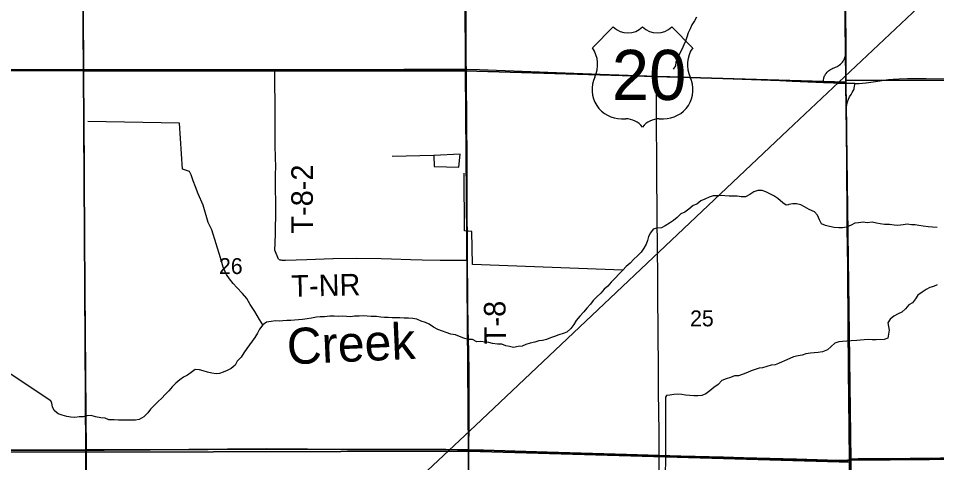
# Model space of a CAD drawing. Extents: x 0 to 34, y 0 to 22.
# Drawn here: x 5.327 to 7.743, y 16.618 to 17.786 of the extents above; entities that cross this region are included whole.
import ezdxf

# ---------------------------------------------------------------- set-up
doc = ezdxf.new("R2010")
doc.units = 0
for name, color, linetype in [('Default', 7, 'Continuous'), ('GM_X_County_Road', 7, 'Continuous'), ('GM_X_Minor_Lake', 7, 'Continuous'), ('GM_X_Minor_River', 7, 'Continuous'), ('GM_X_Minor_River_Text', 7, 'Continuous'), ('GM_X_Rail_Line', 7, 'Continuous'), ('GM_X_Section', 7, 'Continuous'), ('GM_X_Section_Text', 7, 'Continuous'), ('GM_X_State_Route', 7, 'Continuous'), ('GM_X_Township_Road', 7, 'Continuous'), ('GM_X_Township_Road_Text', 7, 'Continuous'), ('GM_X_US_Location', 7, 'Continuous'), ('GM_X_US_Route', 7, 'Continuous'), ('GM_X_US_Shield', 7, 'Continuous')]:
    doc.layers.add(name, color=color, linetype=linetype)

msp = doc.modelspace()

# ---------------------------------------------------------------- linework, layer by layer
at = {"layer": 'Default'}
for points in [[(5.2793, 16.6503), (5.5058, 16.651), (5.5529, 16.6511), (5.6741, 16.6516), (5.9788, 16.6539), (6.0877, 16.6534), (6.1934, 16.6525), (6.3644, 16.6524), (6.4514, 16.6525), (6.5115, 16.6515), (6.5509, 16.6508), (6.7187, 16.6456), (6.9269, 16.6394), (7.0127, 16.6367), (7.0699, 16.6349), (7.1818, 16.6319), (7.2346, 16.6304), (7.3745, 16.6268), (7.4553, 16.6243), (7.4925, 16.623), (7.5049, 16.6234), (7.5087, 16.6241), (7.5134, 16.6254), (7.5132, 16.6298), (7.5127, 16.7012), (7.5126, 16.7199), (7.512, 16.7728), (7.5112, 16.8754), (7.5101, 16.9656), (7.5098, 17.006), (7.5099, 17.0121), (7.5099, 17.0339), (7.5094, 17.0649), (7.5089, 17.1334), (7.5078, 17.236), (7.5076, 17.2888), (7.5069, 17.3759), (7.5061, 17.4412), (7.506, 17.4536), (7.5054, 17.5157), (7.5051, 17.5394), (7.505, 17.5475), (7.5036, 17.6162), (7.504, 17.6965), (7.5041, 17.701), (7.5038, 17.739), (7.5032, 17.7822), (7.5006, 17.9615)], [(7.5006, 17.9615), (7.5032, 17.7822), (7.5038, 17.739), (7.5041, 17.701), (7.504, 17.6965), (7.5036, 17.6162), (7.505, 17.5475), (7.5051, 17.5394), (7.5054, 17.5157), (7.506, 17.4536), (7.5061, 17.4412), (7.5069, 17.3759), (7.5076, 17.2888), (7.5078, 17.236), (7.5089, 17.1334), (7.5094, 17.0649), (7.5099, 17.0339), (7.5099, 17.0121), (7.5098, 17.006), (7.5101, 16.9656), (7.5112, 16.8754), (7.512, 16.7728), (7.5126, 16.7199), (7.5127, 16.7012), (7.5132, 16.6298), (7.5134, 16.6254), (7.5154, 16.6261), (7.5175, 16.6266), (7.5197, 16.6269), (7.5217, 16.6271), (7.5232, 16.6271), (7.5362, 16.6274), (7.5767, 16.6277), (7.6731, 16.6285), (7.8317, 16.6301)], [(7.5138, 16.5271), (7.5134, 16.6254), (7.5087, 16.6241), (7.5049, 16.6234), (7.4925, 16.623), (7.4553, 16.6243), (7.3745, 16.6268), (7.2346, 16.6304), (7.1818, 16.6319), (7.0699, 16.6349), (7.0127, 16.6367), (6.9269, 16.6394), (6.7187, 16.6456), (6.5509, 16.6508), (6.5115, 16.6515), (6.4514, 16.6525), (6.3644, 16.6524), (6.1934, 16.6525), (6.0877, 16.6534), (5.9788, 16.6539), (5.6741, 16.6516), (5.5529, 16.6511), (5.5058, 16.651), (5.2793, 16.6503)], [(7.8317, 16.6301), (7.6731, 16.6285), (7.5767, 16.6277), (7.5362, 16.6274), (7.5232, 16.6271), (7.5217, 16.6271), (7.5197, 16.6269), (7.5175, 16.6266), (7.5154, 16.6261), (7.5134, 16.6254), (7.5138, 16.5271), (7.5145, 16.4463), (7.5165, 16.1851), (7.5171, 16.0545), (7.5184, 15.927), (7.5192, 15.8554), (7.5206, 15.6813), (7.5216, 15.6399), (7.5244, 14.8701), (7.5225, 14.1), (8.9, 14.1)]]:
    msp.add_lwpolyline(points, dxfattribs=at)
at = {"layer": 'GM_X_County_Road'}
for points in [[(7.4449, 17.618), (7.4449, 17.6219), (7.4452, 17.6249), (7.4456, 17.628), (7.4459, 17.6297), (7.447, 17.6328), (7.448, 17.6354), (7.4491, 17.6372), (7.4506, 17.6395), (7.4524, 17.6418), (7.4546, 17.6445), (7.4569, 17.6466), (7.4586, 17.6483), (7.4611, 17.65), (7.4638, 17.6517), (7.4668, 17.6536), (7.4699, 17.6552), (7.4734, 17.6567), (7.4765, 17.6578), (7.4794, 17.659), (7.4816, 17.6602), (7.4841, 17.6616), (7.4866, 17.6634), (7.49, 17.6659), (7.4949, 17.6711), (7.4969, 17.6738), (7.4987, 17.677), (7.4994, 17.6782), (7.5006, 17.6808), (7.5016, 17.6838), (7.5029, 17.688), (7.5036, 17.6916), (7.5042, 17.6959), (7.5043, 17.7004), (7.5041, 17.7384), (7.5035, 17.7817), (7.5008, 17.961)], [(7.5039, 17.6156), (7.4834, 17.616), (7.4582, 17.6174), (7.4449, 17.618)], [(7.5277, 17.6151), (7.5268, 17.6151), (7.5039, 17.6156)], [(7.5136, 16.6249), (7.5134, 16.6292), (7.513, 16.7007), (7.5129, 16.7193), (7.5123, 16.7722), (7.5114, 16.8748), (7.5103, 16.965), (7.51, 17.0054), (7.5101, 17.0115), (7.5101, 17.0333), (7.5096, 17.0644), (7.5092, 17.1328), (7.5081, 17.2354), (7.5079, 17.2883), (7.5071, 17.3753), (7.5063, 17.4406), (7.5063, 17.4531), (7.5056, 17.5151), (7.5053, 17.5388), (7.5052, 17.5469), (7.5054, 17.5527), (7.5063, 17.5594), (7.5081, 17.567), (7.5109, 17.5743), (7.5138, 17.5799), (7.5175, 17.5864), (7.5208, 17.5918), (7.523, 17.5954), (7.5248, 17.5987), (7.5256, 17.6009), (7.5261, 17.6029), (7.5268, 17.6073), (7.5273, 17.6123), (7.5277, 17.6151)], [(5.0035, 16.6486), (5.065, 16.6487), (5.2795, 16.6497), (5.5061, 16.6504)], [(5.5061, 16.6504), (5.5531, 16.6506), (5.6744, 16.651), (5.9791, 16.6533), (6.0879, 16.6528), (6.1936, 16.6519), (6.3646, 16.6519), (6.4517, 16.652), (6.5118, 16.6509)], [(6.5118, 16.6509), (6.5511, 16.6502), (6.7189, 16.6451), (6.9272, 16.6389), (7.0129, 16.6361)], [(7.0129, 16.6361), (7.0701, 16.6343), (7.182, 16.6313), (7.2348, 16.6298), (7.3747, 16.6263), (7.4555, 16.6237), (7.4927, 16.6225), (7.5051, 16.6228), (7.5089, 16.6235), (7.5136, 16.6249)], [(7.5136, 16.6249), (7.5156, 16.6255), (7.5177, 16.626), (7.5199, 16.6263), (7.5219, 16.6265), (7.5235, 16.6265), (7.5365, 16.6268), (7.5769, 16.6271), (7.6733, 16.628), (7.8319, 16.6295), (7.9034, 16.63), (7.9967, 16.6306), (8.0838, 16.6311), (8.1584, 16.6316), (8.2952, 16.6318), (8.3854, 16.6323), (8.4383, 16.6327), (8.4973, 16.6329), (8.6217, 16.6331), (8.6592, 16.6332)], [(7.5219, 15.6393), (7.5208, 15.6808), (7.5195, 15.8549), (7.5186, 15.9264), (7.5174, 16.0539), (7.5167, 16.1845), (7.5147, 16.4457), (7.5141, 16.5265), (7.5136, 16.6249)]]:
    msp.add_lwpolyline(points, dxfattribs=at)
at = {"layer": 'GM_X_Minor_Lake'}
msp.add_line((6.4205, 17.4253), (6.4213, 17.3969), dxfattribs=at)
msp.add_lwpolyline([(6.4213, 17.3969), (6.4861, 17.3947), (6.4891, 17.4292), (6.4205, 17.4253)], dxfattribs=at)
at = {"layer": 'GM_X_Minor_River'}
for points in [[(7.1107, 17.79), (7.1056, 17.7798), (7.0987, 17.7692), (7.0944, 17.759), (7.089, 17.7484), (7.0855, 17.7371), (7.0823, 17.7265), (7.0777, 17.7167), (7.0726, 17.7042), (7.066, 17.6929), (7.0621, 17.6823), (7.0571, 17.6725), (7.0558, 17.6619), (7.0493, 17.6532)], [(5.97, 16.9801), (5.9618, 16.9943), (5.9492, 17.0153), (5.9369, 17.034), (5.9283, 17.0492), (5.9167, 17.063), (5.9017, 17.0783), (5.8924, 17.0887), (5.8823, 17.1013), (5.8748, 17.1128), (5.8659, 17.1322), (5.8586, 17.1566), (5.836, 17.23), (5.8267, 17.2498), (5.8136, 17.2951), (5.8002, 17.3249), (5.7932, 17.3435), (5.7874, 17.3591), (5.7818, 17.3751), (5.7774, 17.3839), (5.7589, 17.3894), (5.7511, 17.5109), (5.5104, 17.5148)], [(6.4205, 17.4253), (6.3105, 17.423)], [(6.9171, 17.124), (6.5215, 17.1386), (6.5202, 17.2259), (6.5005, 17.2276), (6.5003, 17.379)], [(7.3534, 17.2956), (7.3471, 17.2954), (7.338, 17.3008), (7.3253, 17.3127), (7.3143, 17.3197), (7.3042, 17.3251), (7.2936, 17.3305), (7.2834, 17.334), (7.2724, 17.3334), (7.2618, 17.3297), (7.2511, 17.3229), (7.2404, 17.317), (7.229, 17.3171), (7.218, 17.3187), (7.2082, 17.3188), (7.1968, 17.3189), (7.1858, 17.3198), (7.176, 17.3207), (7.1654, 17.3196), (7.1551, 17.3197), (7.1441, 17.316), (7.1334, 17.3112), (7.1227, 17.306), (7.112, 17.2974), (7.1025, 17.2945), (7.091, 17.2843), (7.08, 17.2768), (7.0697, 17.272), (7.0601, 17.263), (7.0505, 17.2551), (7.0402, 17.2473), (7.0291, 17.2405), (7.0188, 17.2353), (7.0071, 17.2347), (6.9968, 17.2321), (6.9899, 17.2223), (6.9845, 17.2125), (6.9825, 17.2023), (6.9785, 17.1921), (6.9724, 17.1823), (6.9658, 17.1713), (6.9562, 17.1616), (6.9459, 17.153), (6.9363, 17.1424), (6.9263, 17.1338), (6.9171, 17.124), (6.9079, 17.1142), (6.8968, 17.103), (6.8864, 17.0925), (6.878, 17.0819), (6.868, 17.0737), (6.8592, 17.0631), (6.8489, 17.0541), (6.8389, 17.0444), (6.832, 17.0346), (6.8227, 17.0244), (6.8151, 17.0146), (6.8039, 17.003), (6.7947, 16.9917), (6.7881, 16.9815), (6.7808, 16.9709), (6.7701, 16.9612), (6.7606, 16.9575), (6.7492, 16.9538), (6.7377, 16.9494), (6.7271, 16.946), (6.7168, 16.942), (6.7062, 16.9387), (6.6963, 16.938), (6.6856, 16.9343), (6.6735, 16.9322), (6.6624, 16.9285), (6.6525, 16.924), (6.6419, 16.923), (6.6301, 16.9208), (6.6192, 16.9236), (6.6093, 16.9252), (6.5988, 16.9295), (6.5874, 16.9292), (6.5749, 16.9312), (6.5651, 16.9336), (6.5548, 16.9349), (6.5435, 16.9365), (6.5336, 16.9358), (6.5216, 16.9416), (6.5102, 16.9418), (6.4992, 16.9453), (6.4879, 16.9496), (6.4773, 16.9535), (6.4645, 16.9559), (6.4524, 16.9602), (6.4426, 16.9633), (6.4309, 16.968), (6.4196, 16.9745), (6.4079, 16.9819), (6.3981, 16.9865), (6.3871, 16.9897), (6.3758, 16.9951), (6.3645, 16.9971), (6.3531, 16.9976), (6.3417, 16.9977)], [(7.7445, 17.2361), (7.7316, 17.237), (7.7206, 17.2383), (7.7074, 17.2399), (7.6961, 17.2419), (7.6862, 17.2432), (7.6764, 17.2433), (7.665, 17.2449), (7.6544, 17.2431), (7.6407, 17.2418), (7.6309, 17.2423), (7.6188, 17.2439), (7.6059, 17.2444), (7.5946, 17.246), (7.5843, 17.2477), (7.5734, 17.2501), (7.5597, 17.2483), (7.5491, 17.2503), (7.5374, 17.2485), (7.5279, 17.2475), (7.518, 17.2427), (7.5058, 17.2371), (7.4951, 17.2357), (7.4857, 17.235), (7.4736, 17.2367), (7.4611, 17.2387), (7.4501, 17.2415), (7.4396, 17.2461), (7.4348, 17.2564), (7.4296, 17.2683), (7.4214, 17.2778), (7.4075, 17.284), (7.3954, 17.2906), (7.3853, 17.296), (7.3743, 17.2984), (7.3641, 17.2989), (7.3542, 17.2964), (7.3534, 17.2956)], [(7.7441, 17.0852), (7.7342, 17.0811), (7.7247, 17.0782), (7.7148, 17.0733), (7.7048, 17.0658), (7.6933, 17.058), (7.6872, 17.0482), (7.6791, 17.0384), (7.6695, 17.0328), (7.6611, 17.0219), (7.6515, 17.0133), (7.6412, 17.0092), (7.6301, 17.0029), (7.6202, 16.9954), (7.6147, 16.9852), (7.6161, 16.9754), (7.6175, 16.9659), (7.6163, 16.9553), (7.6142, 16.9454), (7.6047, 16.9413), (7.5835, 16.9408), (7.5736, 16.9405), (7.563, 16.9414), (7.552, 16.9411), (7.5422, 16.9397), (7.5327, 16.9391), (7.5183, 16.9377), (7.5069, 16.9374), (7.4951, 16.9368), (7.4853, 16.9354), (7.4754, 16.9321), (7.4654, 16.9231), (7.4555, 16.9148), (7.4429, 16.9089), (7.4307, 16.9071), (7.4205, 16.9069), (7.4106, 16.9054), (7.3989, 16.904), (7.3893, 16.9), (7.3783, 16.8986), (7.3666, 16.8957)], [(6.3417, 16.9977), (6.3311, 16.9989), (6.3213, 16.9987), (6.3107, 16.9984), (6.3001, 16.9992), (6.2902, 16.9993), (6.2804, 17.0002), (6.2694, 17.0018), (6.2554, 17.0023), (6.2444, 17.0028), (6.2341, 17.0037), (6.2235, 17.003), (6.2114, 17.0028), (6.2008, 17.0014), (6.1905, 17.0022), (6.1807, 17.0027), (6.1693, 17.0021), (6.1579, 17.0026), (6.1462, 17.0031), (6.1325, 17.0017), (6.1211, 17.001), (6.1113, 17), (6.098, 16.9978), (6.0866, 16.9957), (6.0744, 16.9939), (6.0646, 16.9932), (6.0536, 16.9926), (6.0441, 16.9912), (6.0331, 16.9913), (6.0232, 16.9906), (6.0137, 16.9903), (6.0039, 16.9908), (5.9921, 16.9894), (5.9799, 16.9869), (5.97, 16.9801), (5.9615, 16.9688), (5.9565, 16.9586), (5.9492, 16.9473), (5.9422, 16.9375), (5.9353, 16.9274), (5.9284, 16.9176), (5.9207, 16.9063), (5.9137, 16.8949), (5.9026, 16.8848), (5.8972, 16.8742), (5.8872, 16.8652), (5.8769, 16.8604), (5.8663, 16.856), (5.8567, 16.8523), (5.8473, 16.8512), (5.8359, 16.8528), (5.8249, 16.856), (5.8136, 16.8595), (5.8038, 16.8619), (5.792, 16.8628), (5.7821, 16.8545), (5.7718, 16.8482), (5.7615, 16.8422), (5.7519, 16.8351), (5.7416, 16.8265), (5.7316, 16.8171), (5.7232, 16.8065), (5.7132, 16.7968), (5.7044, 16.787), (5.6948, 16.7787), (5.6852, 16.7693), (5.6749, 16.7588), (5.6675, 16.749), (5.6572, 16.7381), (5.6453, 16.731), (5.6355, 16.7292), (5.6203, 16.7298), (5.6104, 16.7291), (5.5998, 16.7296), (5.5904, 16.7293), (5.5794, 16.7302), (5.565, 16.7307), (5.5552, 16.7346), (5.5442, 16.7358), (5.5302, 16.7386), (5.5185, 16.7414), (5.5078, 16.7407), (5.4976, 16.7382), (5.487, 16.7383), (5.4756, 16.7361), (5.465, 16.737), (5.4544, 16.739), (5.4423, 16.7422), (5.4321, 16.746), (5.4216, 16.7549), (5.4175, 16.7644), (5.415, 16.7739), (5.4128, 16.7804)], [(5.4128, 16.7804), (5.1824, 16.9329)], [(7.3406, 16.8849), (7.3367, 16.8831), (7.3272, 16.8786), (7.3177, 16.8753), (7.3078, 16.8739), (7.285, 16.8673), (7.2755, 16.8662), (7.2546, 16.8596), (7.2451, 16.8551), (7.2336, 16.8507), (7.2214, 16.8459), (7.2112, 16.846), (7.2009, 16.8419), (7.1891, 16.8382), (7.1781, 16.8334), (7.1685, 16.8236), (7.1566, 16.815), (7.1459, 16.8068), (7.1356, 16.7985), (7.1249, 16.7941), (7.1147, 16.7938), (7.1041, 16.7936), (7.0939, 16.7944), (7.0825, 16.7953), (7.0723, 16.7973), (7.0613, 16.7978), (7.0518, 16.7967), (7.0412, 16.7953), (7.0322, 16.7945), (7.0297, 16.7897)], [(7.3666, 16.8957), (7.3406, 16.8849)], [(7.0297, 16.7897), (7.029, 16.4232), (7.0051, 16.4238), (7.0024, 16.1814)]]:
    msp.add_lwpolyline(points, dxfattribs=at)
at = {"layer": 'GM_X_Rail_Line'}
msp.add_lwpolyline([(5.6036, 14.1), (5.6231, 15.2124), (5.6254, 15.4429), (5.6392, 15.5731), (5.6554, 15.6619), (5.6784, 15.7322), (5.7095, 15.8198), (5.7429, 15.8889), (5.7752, 15.9442), (5.8121, 16.0007), (5.8512, 16.0606), (5.9042, 16.1217), (5.9987, 16.2174), (6.5299, 16.7153), (7.3509, 17.4922), (8.0819, 18.1807), (8.7161, 18.7707), (8.9, 18.9438)], dxfattribs=at)
at = {"layer": 'GM_X_Section'}
for points in [[(4.4846, 18.6535), (5.4908, 18.6512), (5.4987, 17.6483), (4.4933, 17.6509)], [(5.4908, 18.6512), (6.4992, 18.6508), (6.5031, 17.6487), (5.4987, 17.6483)], [(6.4992, 18.6508), (7.4929, 18.6076), (7.5039, 17.6243), (7.5038, 17.6183), (6.5031, 17.6487)], [(7.4927, 18.6151), (8.6395, 18.6159), (8.6491, 17.6213), (7.5039, 17.6243), (7.4929, 18.6076)], [(4.4933, 17.6509), (5.4987, 17.6483), (5.5052, 16.6454), (4.5021, 16.6472)], [(5.4987, 17.6483), (6.5031, 17.6487), (6.5111, 16.648), (5.5052, 16.6454)], [(6.5031, 17.6487), (7.5038, 17.6183), (7.5172, 16.6244), (7.5171, 16.6191), (6.5111, 16.648)], [(7.5039, 17.6243), (8.6491, 17.6213), (8.6573, 16.6339), (7.5172, 16.6244), (7.5038, 17.6183)], [(4.5021, 16.6472), (5.5052, 16.6454), (5.5125, 15.6443), (4.5104, 15.6416)], [(5.5052, 16.6454), (6.5111, 16.648), (6.5138, 15.6467), (5.5125, 15.6443)], [(6.5111, 16.648), (7.5171, 16.6191), (7.5223, 15.6321), (6.5138, 15.6467)], [(7.5172, 16.6244), (8.6573, 16.6339), (8.6614, 15.6262), (7.5223, 15.6321), (7.5171, 16.6191)]]:
    msp.add_lwpolyline(points, close=True, dxfattribs=at)
at = {"layer": 'GM_X_State_Route'}
for points in [[(5.4994, 17.652), (5.4992, 17.672), (5.4983, 17.787), (5.4981, 17.8181), (5.4981, 17.828), (5.4981, 17.8523), (5.4963, 17.9797), (5.4953, 18.0979), (5.494, 18.2004), (5.4935, 18.2378), (5.4913, 18.4833), (5.4897, 18.6357), (5.4896, 18.6535), (5.4893, 18.6854), (5.4887, 18.8626), (5.4886, 18.9093), (5.4885, 18.9621), (5.4881, 19.0056), (5.4877, 19.0709), (5.4874, 19.1734), (5.4864, 19.4408)], [(5.5061, 16.6504), (5.5054, 16.7424), (5.5044, 16.8606), (5.504, 16.9569), (5.5017, 17.3207), (5.5012, 17.4046), (5.5006, 17.501), (5.4994, 17.652)], [(5.507, 16.5341), (5.5061, 16.6504)]]:
    msp.add_lwpolyline(points, dxfattribs=at)
at = {"layer": 'GM_X_Township_Road'}
for points in [[(6.5059, 17.6525), (6.5054, 17.6677), (6.5051, 17.7796), (6.5047, 17.8728), (6.5046, 17.9008), (6.5044, 17.9443), (6.5042, 18.0344), (6.5029, 18.1432), (6.502, 18.1898), (6.5016, 18.2458), (6.5011, 18.3763), (6.5004, 18.4416), (6.5, 18.5131), (6.4994, 18.6001), (6.4986, 18.6529), (6.4986, 18.6541)], [(6.0115, 17.1532), (6.0023, 17.1765), (6.003, 17.1953), (6.0036, 17.2203), (6.0042, 17.2828), (6.004, 17.3579), (6.0036, 17.3786), (6.0042, 17.394), (6.0032, 17.4502), (6.0031, 17.4689), (6.0027, 17.5407), (6.0026, 17.5688), (6.0022, 17.6094), (6.0022, 17.6343), (6.002, 17.6406), (6.0017, 17.6519)], [(6.5089, 17.1507), (6.5084, 17.1922), (6.5081, 17.2854), (6.5076, 17.4346), (6.507, 17.4967), (6.5062, 17.6428), (6.5059, 17.6525)], [(7.0129, 16.6361), (7.0128, 16.6482), (7.0125, 16.698), (7.0115, 16.8037), (7.0108, 16.8877), (7.0103, 16.9375), (7.0093, 17.0836), (7.009, 17.1178), (7.0085, 17.1707), (7.0069, 17.3759), (7.0066, 17.4195), (7.0062, 17.5035), (7.0056, 17.5532), (7.005, 17.6248), (7.005, 17.6346)], [(6.0115, 17.1532), (6.0147, 17.1516), (6.0176, 17.1508), (6.0207, 17.1503), (6.03, 17.1501), (6.0579, 17.1513), (6.0858, 17.1525), (6.1541, 17.1545), (6.1551, 17.1545)], [(6.1551, 17.1545), (6.2161, 17.1553), (6.2813, 17.1548), (6.3092, 17.1538), (6.3588, 17.1517), (6.3898, 17.1512), (6.4364, 17.1507), (6.5089, 17.1507)], [(6.5118, 16.6509), (6.5119, 16.6576), (6.513, 16.7167), (6.5131, 16.7695), (6.5127, 16.8534), (6.512, 16.9124), (6.5108, 16.9684), (6.5097, 17.043), (6.5092, 17.0709), (6.5091, 17.1362), (6.5089, 17.1507)], [(5.0035, 16.6486), (5.065, 16.6487), (5.2795, 16.6497), (5.5061, 16.6504)], [(5.5061, 16.6504), (5.5531, 16.6506), (5.6744, 16.651), (5.9791, 16.6533), (6.0879, 16.6528), (6.1936, 16.6519), (6.3646, 16.6519), (6.4517, 16.652), (6.5118, 16.6509)], [(6.5149, 16.1915), (6.5149, 16.1968), (6.5147, 16.2216), (6.5142, 16.2961), (6.5127, 16.4952), (6.5118, 16.6008), (6.5118, 16.6509)], [(6.5118, 16.6509), (6.5511, 16.6502), (6.7189, 16.6451), (6.9272, 16.6389), (7.0129, 16.6361)], [(7.0152, 16.1383), (7.0155, 16.1476), (7.0159, 16.2345), (7.0139, 16.4585), (7.0129, 16.5891), (7.0125, 16.6233), (7.0129, 16.6361)], [(7.0129, 16.6361), (7.0701, 16.6343), (7.182, 16.6313), (7.2348, 16.6298), (7.3747, 16.6263), (7.4555, 16.6237), (7.4927, 16.6225), (7.5051, 16.6228), (7.5089, 16.6235), (7.5136, 16.6249)]]:
    msp.add_lwpolyline(points, dxfattribs=at)
at = {"layer": 'GM_X_US_Route'}
msp.add_line((7.3626, 17.6215), (7.4449, 17.618), dxfattribs=at)
for points in [[(5.0334, 17.6517), (5.2384, 17.6517), (5.4056, 17.6521), (5.4994, 17.652)], [(5.4994, 17.652), (5.5479, 17.6519), (5.623, 17.6517), (5.6849, 17.6518), (5.716, 17.6519), (5.9182, 17.6522), (5.9836, 17.6519), (6.0017, 17.6519), (6.0116, 17.6519), (6.0489, 17.6522), (6.1112, 17.6523), (6.3415, 17.6527), (6.413, 17.6527), (6.4628, 17.6529), (6.5059, 17.6525), (6.5406, 17.6517), (6.7427, 17.6441), (6.8577, 17.6399), (7.005, 17.6346), (7.0412, 17.6333), (7.2309, 17.6265), (7.3304, 17.6228), (7.3626, 17.6215)], [(7.4449, 17.618), (7.4582, 17.6174), (7.4834, 17.616), (7.5039, 17.6156)], [(7.5039, 17.6156), (7.5268, 17.6151), (7.5277, 17.6151)], [(7.5277, 17.6151), (7.5392, 17.6154), (7.5567, 17.6169)], [(7.5567, 17.6169), (7.5577, 17.6169), (7.5761, 17.6192), (7.6161, 17.6252), (7.6285, 17.6266), (7.644, 17.6275), (7.6658, 17.628), (7.7155, 17.628), (7.7807, 17.6276)]]:
    msp.add_lwpolyline(points, dxfattribs=at)
at = {"layer": 'GM_X_US_Shield'}
for p, q in [((6.8923, 17.7639), (6.8373, 17.709)), ((7.101, 17.709), (7.0461, 17.7639)), ((6.9142, 17.5222), (6.9252, 17.5222)), ((7.0131, 17.5222), (7.0241, 17.5222))]:
    msp.add_line(p, q, dxfattribs=at)
for centre, radius, start, end in [((6.9307, 17.8032), 0.0549, 225.573, 314.427), ((7.0076, 17.8032), 0.0549, 225.573, 314.427), ((6.7743, 17.6649), 0.0769, 334.5471, 35.0009), ((7.164, 17.6649), 0.0769, 144.9991, 205.4529), ((6.9134, 17.5991), 0.0769, 154.8319, 270.6383), ((7.025, 17.5991), 0.0769, 269.3617, 25.1681), ((6.9252, 17.4673), 0.0549, 36.8699, 90), ((7.0131, 17.4673), 0.0549, 90, 143.1301)]:
    msp.add_arc(centre, radius, start, end, dxfattribs=at)

# ---------------------------------------------------------------- texts
at = {"layer": 'GM_X_Minor_River_Text'}
msp.add_text('Creek', height=0.09477, rotation=2.5646, dxfattribs=at).set_placement((6.0357, 16.8759))
at = {"layer": 'GM_X_Section_Text'}
for s, p in [('26', (5.855, 17.1138)), ('25', (7.0942, 16.9763))]:
    msp.add_text(s, height=0.04186, rotation=0, dxfattribs=at).set_placement(p)
at = {"layer": 'GM_X_Township_Road_Text'}
for s, rotation, p in [('T-8-2', 90, (6.102, 17.2204)), ('T-NR', 1.4617, (6.0462, 17.0536)), ('T-8', 90.9539, (6.6103, 16.9298))]:
    msp.add_text(s, height=0.05682, rotation=rotation, dxfattribs=at).set_placement(p)
at = {"layer": 'GM_X_US_Location'}
for s in ['0', '/']:
    msp.add_text(s, height=0.000189, dxfattribs=at).set_placement((6.9691, 17.6365))
msp.add_text('20', height=0.000189, rotation=0, dxfattribs=at).set_placement((6.93, 17.5973))
at = {"layer": 'GM_X_US_Shield'}
msp.add_text('20', height=0.13184, dxfattribs=at).set_placement((6.8883, 17.5717))

doc.saveas('drawing.dxf')
